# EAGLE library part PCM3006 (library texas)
16-Bit, Single-Ended Analog Input/Output Stereo Audio Codec Source: http://focus.ti.com/lit/ds/symlink/pcm3006.pdf
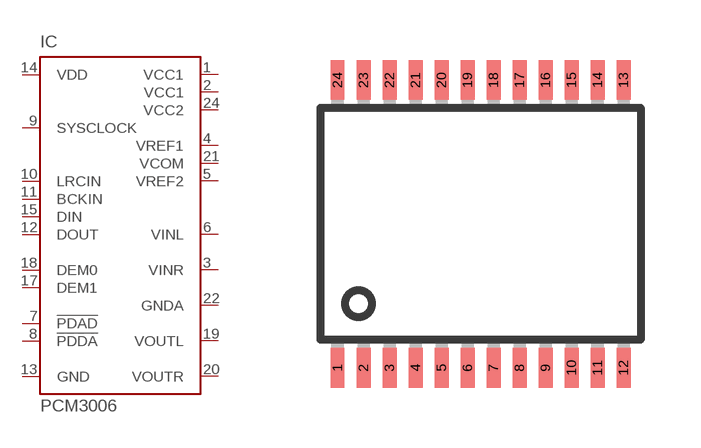
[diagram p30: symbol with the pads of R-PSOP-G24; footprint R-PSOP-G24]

Designator prefix IC

## PCM3006 (MF: TEXAS INSTRUMENT CONNECTORS; MPN: PCM3006T; OC_FARNELL: 1510088; OC_NEWARK: 75C5392)  [R-PSOP-G24]
1  VCC1  pwr
2  VCC1  pwr
3  VINR  in
4  VREF1  pas
5  VREF2  pas
6  VINL  in
7  !PDAD  in
8  !PDDA  in
9  SYSCLOCK  in
10  LRCIN  in
11  BCKIN  in
12  DOUT  in
13  GND  pwr
14  VDD  pwr
15  DIN  in
17  DEM1  in
18  DEM0  in
19  VOUTL  out
20  VOUTR  out
21  VCOM  pwr
22  GNDA  pwr
24  VCC2  pwr

## Footprint R-PSOP-G24 (pad centres in mm)
DCV (R-PSOP-G24) PLASTIC SMALL-OUTLINE Source: http://focus.ti.com/lit/ds/symlink/pcm3006.pdf
smd 0.35 x 1: 1 -3.575,-3.6; 2 -2.925,-3.6; 3 -2.275,-3.6; 4 -1.625,-3.6; 5 -0.975,-3.6; 6 -0.325,-3.6; 7 0.325,-3.6; 8 0.975,-3.6; 9 1.625,-3.6; 10 2.275,-3.6; 11 2.925,-3.6; 12 3.575,-3.6; 13 3.575,3.6; 14 2.925,3.6; 15 2.275,3.6; 16 1.625,3.6; 17 0.975,3.6; 18 0.325,3.6; 19 -0.325,3.6; 20 -0.975,3.6; 21 -1.625,3.6; 22 -2.275,3.6; 23 -2.925,3.6; 24 -3.575,3.6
